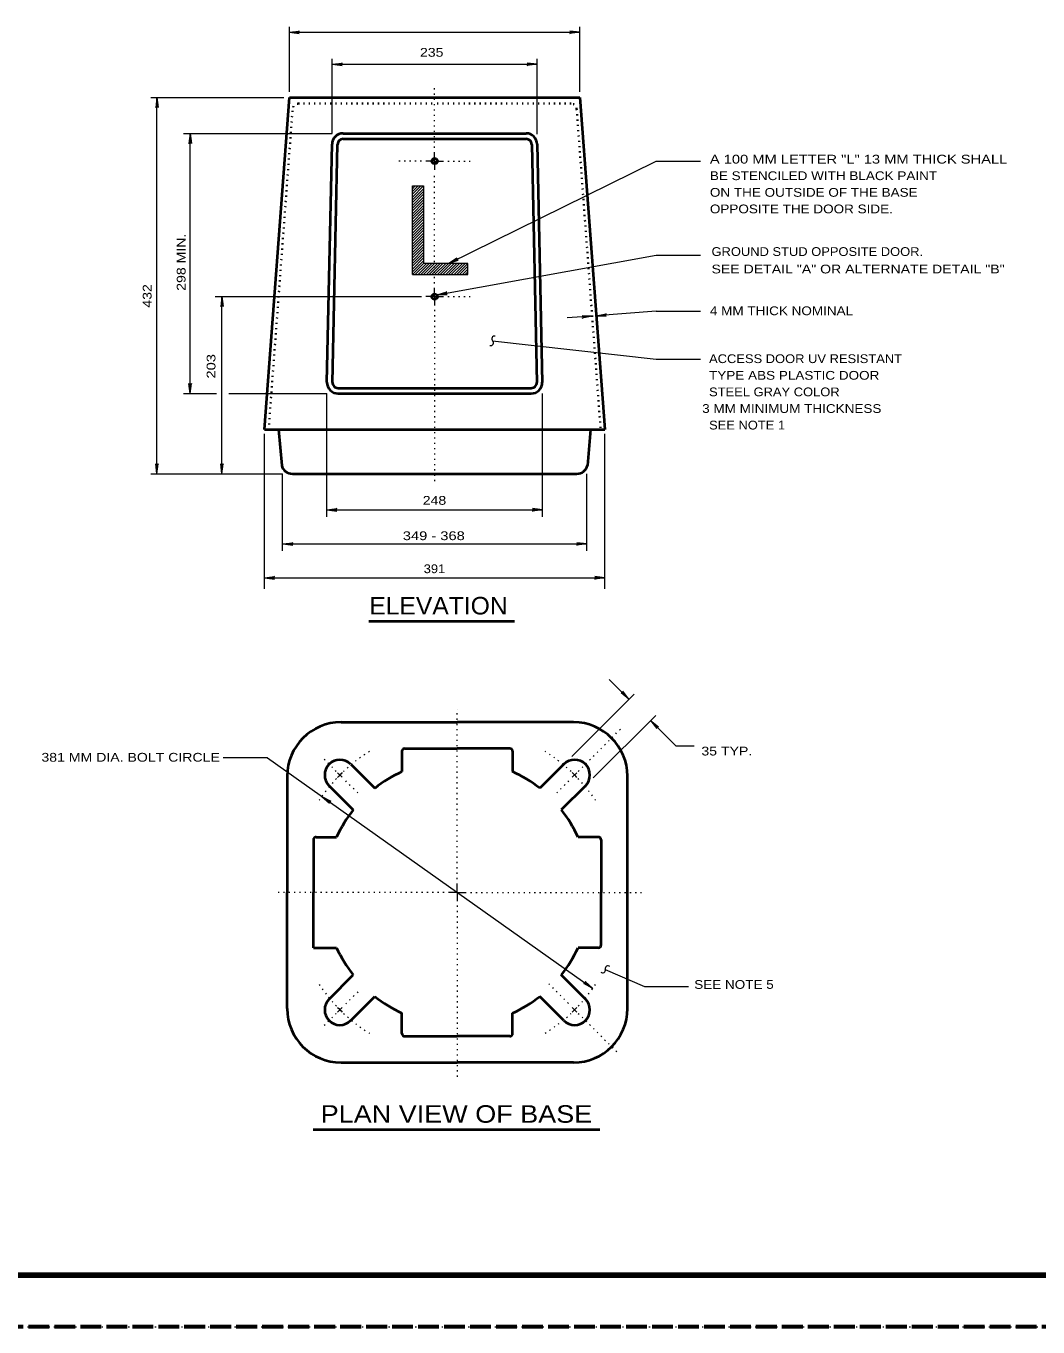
# Model space of a CAD drawing. Extents: x 312583 to 312854, y 144419 to 144597.
# Drawn here: x 312633.7 to 312721.4, y 144418.6 to 144531.2 of the extents above; entities that cross this region are included whole.
import ezdxf
from ezdxf.enums import TextEntityAlignment as Align

# ---------------------------------------------------------------- set-up
doc = ezdxf.new("R2010")
doc.units = 0
doc.header["$LTSCALE"] = 0.3
doc.linetypes.add('DOTTED', pattern=[1.5, 0.3, -1.2])
doc.linetypes.add('LONG_DASHED', pattern=[7.5, 6, -1.5])
for name, color, linetype, lineweight in [('1', 7, 'Continuous', 40), ('2', 7, 'Continuous', 13), ('62', 7, 'DOTTED', 13), ('63', 7, 'LONG_DASHED', 60)]:
    doc.layers.add(name, color=color, linetype=linetype, lineweight=lineweight)

msp = doc.modelspace()

# ---------------------------------------------------------------- linework, layer by layer
at = {"layer": '1', "linetype": 'DOTTED', "lineweight": 35}
for p in [(312657.3091, 144524.5084), (312680.9378, 144524.5084)]:
    msp.add_line(p, (312669.1235, 144524.5084), dxfattribs=at)
at = {"layer": '1'}
for p, q in [((312655.6148, 144496.295), (312655.8831, 144493.1824)), ((312682.6321, 144496.295), (312682.3638, 144493.1824)), ((312661.0266, 144470.9443), (312671.0853, 144470.9443)), ((312681.1516, 144470.9443), (312671.0853, 144470.9443)), ((312666.2936, 144468.4297), (312666.2936, 144466.6663)), ((312666.5313, 144468.675), (312671.0853, 144468.675)), ((312675.6393, 144468.675), (312671.0853, 144468.675)), ((312675.8769, 144468.4297), (312675.8769, 144466.6663)), ((312661.8546, 144467.3103), (312663.9399, 144465.225)), ((312680.3159, 144467.3103), (312678.2306, 144465.225)), ((312656.3499, 144466.2753), (312656.3499, 144456.2167)), ((312685.8206, 144456.2167), (312685.8206, 144466.2753)), ((312659.9916, 144465.4473), (312662.0769, 144463.362)), ((312682.1789, 144465.4473), (312680.0936, 144463.362)), ((312658.6269, 144460.763), (312658.6269, 144456.2167)), ((312658.8646, 144461.0083), (312660.6356, 144461.0083)), ((312683.3059, 144461.0083), (312681.5426, 144461.0083)), ((312683.5436, 144460.763), (312683.5436, 144456.2167)), ((312656.3499, 144446.1503), (312656.3499, 144456.2167)), ((312658.6269, 144451.425), (312658.6269, 144456.2167)), ((312683.5436, 144451.6627), (312683.5436, 144456.2167)), ((312685.8206, 144446.1503), (312685.8206, 144456.2167)), ((312658.6269, 144451.425), (312660.6356, 144451.425)), ((312683.3059, 144451.425), (312681.5426, 144451.425)), ((312659.9916, 144446.9783), (312662.0769, 144449.0713)), ((312682.1789, 144446.9783), (312680.0936, 144449.0637)), ((312661.8546, 144445.1153), (312663.9399, 144447.2007)), ((312680.3159, 144445.1153), (312678.2306, 144447.2007)), ((312666.2936, 144443.996), (312666.2936, 144445.7593)), ((312675.8769, 144443.996), (312675.8769, 144445.7593)), ((312666.5313, 144443.7583), (312671.0853, 144443.7583)), ((312675.6393, 144443.7583), (312671.0853, 144443.7583)), ((312661.0266, 144441.4813), (312671.0853, 144441.4813)), ((312681.1516, 144441.4813), (312671.0853, 144441.4813))]:
    msp.add_line(p, q, dxfattribs=at)
at = {"layer": '1', "linetype": 'DOTTED', "lineweight": 13}
for p, q in [((312681.5656, 144466.6893), (312685.3836, 144470.515)), ((312660.6049, 144466.6893), (312659.4933, 144467.8087)), ((312662.4756, 144464.8263), (312661.2336, 144466.0607)), ((312679.6949, 144464.8263), (312680.9369, 144466.0607)), ((312679.0049, 144448.297), (312680.9369, 144446.365)), ((312662.4756, 144447.5993), (312661.2336, 144446.365)), ((312660.6049, 144445.7363), (312659.4933, 144444.617)), ((312681.5656, 144445.7363), (312685.0003, 144442.3017))]:
    msp.add_line(p, q, dxfattribs=at)
at = {"layer": '1', "lineweight": 13}
for p, q in [((312661.1263, 144466.1757), (312660.7199, 144466.5743)), ((312681.0443, 144466.1757), (312681.4506, 144466.5743)), ((312661.1263, 144446.2577), (312660.7199, 144445.8513)), ((312681.0443, 144446.2577), (312681.4506, 144445.8513))]:
    msp.add_line(p, q, dxfattribs=at)
at = {"layer": '1', "lineweight": 158}
msp.add_line((312616.5, 144423.0846), (312849, 144423.0846), dxfattribs=at)
at = {"layer": '1'}
for centre in [(312669.1235, 144519.5308), (312669.1235, 144519.5308), (312669.1235, 144507.7912), (312669.1235, 144507.7912)]:
    msp.add_circle(centre, 0.2396, dxfattribs=at)
at = {"layer": '1', "linetype": 'DOTTED', "lineweight": 35}
for centre, start, end in [((312657.3071, 144524.0273), 90, 177.67414), ((312680.936, 144524.0273), 2.32586, 90)]:
    msp.add_arc(centre, 0.4792, start, end, dxfattribs=at)
at = {"layer": '1'}
for centre, radius, start, end in [((312656.812, 144493.4162), 0.9583, 194.04369, 270), ((312681.435, 144493.4162), 0.9583, 270, 345.95631), ((312661.0228, 144466.2753), 4.6719, 90, 180), ((312681.1478, 144466.2753), 4.6719, 0, 90), ((312666.5332, 144468.4316), 0.2396, 90, 180), ((312675.6373, 144468.4316), 0.2396, 0, 90), ((312660.9212, 144466.3769), 1.3177, 45, 225), ((312681.2493, 144466.3769), 1.3177, 315, 135), ((312671.0853, 144456.2128), 11.5, 114.62432, 128.42226), ((312671.0853, 144456.2128), 11.5, 51.58454, 65.37568), ((312671.0853, 144456.2128), 11.5, 141.59134, 155.37568), ((312671.0853, 144456.2128), 11.5, 24.62432, 38.41546), ((312658.8665, 144460.7649), 0.2396, 90, 180), ((312683.304, 144460.7649), 0.2396, 0, 90), ((312671.0853, 144456.2128), 11.5, 204.62432, 218.41546), ((312671.0853, 144456.2128), 11.5, 321.57774, 335.37568), ((312683.304, 144451.6608), 0.2396, 270, 0), ((312660.9212, 144446.0488), 1.3177, 135, 315), ((312671.0853, 144456.2128), 11.5, 231.58454, 245.37568), ((312671.0853, 144456.2128), 11.5, 294.62432, 308.40866), ((312681.2493, 144446.0488), 1.3177, 225, 45), ((312661.0228, 144446.1503), 4.6719, 180, 270), ((312681.1478, 144446.1503), 4.6719, 270, 0), ((312666.5332, 144443.9941), 0.2396, 180, 270), ((312675.6373, 144443.9941), 0.2396, 270, 0)]:
    msp.add_arc(centre, radius, start, end, dxfattribs=at)
at = {"layer": '1', "linetype": 'DOTTED', "lineweight": 13}
for start, end in [(121.96733, 133.24434), (46.75566, 58.03267), (136.75599, 146.30781), (33.69219, 43.24401), (213.69219, 223.24401), (316.75599, 326.30781), (226.75566, 238.03268), (301.96733, 313.24434)]:
    msp.add_arc((312671.0853, 144456.2128), 14.375, start, end, dxfattribs=at)
at = {"layer": '1', "lineweight": 13}
for start, end in [(133.83351, 136.1341), (43.8659, 46.16649), (223.8659, 226.16649), (313.83351, 316.1341)]:
    msp.add_arc((312671.0853, 144456.2128), 14.375, start, end, dxfattribs=at)
at = {"layer": '2'}
for p, q in [((312656.5425, 144525.5204), (312656.5425, 144531.163)), ((312681.7045, 144525.5204), (312681.7045, 144531.163)), ((312656.5195, 144530.6877), (312657.3858, 144530.795)), ((312656.5195, 144530.6877), (312681.7045, 144530.6877)), ((312656.5195, 144530.6877), (312657.3858, 144530.5804)), ((312657.3858, 144530.795), (312657.1098, 144530.6877)), ((312657.3858, 144530.5804), (312657.1098, 144530.6877)), ((312680.8381, 144530.795), (312681.1141, 144530.6877)), ((312681.7045, 144530.6877), (312680.8381, 144530.795)), ((312680.8381, 144530.5804), (312681.1141, 144530.6877)), ((312681.7045, 144530.6877), (312680.8381, 144530.5804)), ((312660.2608, 144521.9247), (312660.2608, 144528.3877)), ((312660.2608, 144527.9124), (312661.1271, 144528.0197)), ((312660.2608, 144527.9124), (312677.9938, 144527.9124)), ((312660.2608, 144527.9124), (312661.1271, 144527.805)), ((312661.1271, 144528.0197), (312660.8511, 144527.9124)), ((312661.1271, 144527.805), (312660.8511, 144527.9124)), ((312677.1275, 144528.0197), (312677.4035, 144527.9124)), ((312677.9938, 144527.9124), (312677.1275, 144528.0197)), ((312677.1275, 144527.805), (312677.4035, 144527.9124)), ((312677.9938, 144527.9124), (312677.1275, 144527.805)), ((312677.9938, 144521.8634), (312677.9938, 144528.3877)), ((312644.5595, 144525.045), (312656.0671, 144525.045)), ((312645.0808, 144525.045), (312644.9735, 144524.1787)), ((312644.9735, 144524.1787), (312645.0808, 144524.4547)), ((312645.0808, 144492.4617), (312645.0808, 144525.045)), ((312645.0808, 144525.045), (312645.1881, 144524.1787)), ((312645.1881, 144524.1787), (312645.0808, 144524.4547)), ((312647.3655, 144521.9247), (312660.2608, 144521.9247)), ((312647.9558, 144521.9247), (312647.8485, 144521.0584)), ((312647.8485, 144521.0584), (312647.9558, 144521.3344)), ((312647.9558, 144499.4077), (312647.9558, 144521.9247)), ((312647.9558, 144521.9247), (312648.0631, 144521.0584)), ((312648.0631, 144521.0584), (312647.9558, 144521.3344)), ((312669.1235, 144519.5327), (312669.1235, 144520.2994)), ((312669.1235, 144519.5327), (312669.1235, 144520.2994)), ((312669.1235, 144519.5327), (312668.3568, 144519.5327)), ((312669.1235, 144519.5327), (312669.8901, 144519.5327)), ((312669.1235, 144519.5327), (312669.1235, 144518.766)), ((312670.3271, 144510.67), (312688.3055, 144519.5174)), ((312688.3055, 144519.5174), (312692.1388, 144519.5174)), ((312667.2068, 144516.42), (312668.1651, 144517.3784)), ((312667.2068, 144516.6577), (312667.9275, 144517.3784)), ((312667.2068, 144516.8954), (312667.6898, 144517.3784)), ((312667.2068, 144517.133), (312667.4521, 144517.3784)), ((312667.2068, 144516.1747), (312668.1651, 144517.133)), ((312667.2068, 144515.937), (312668.1651, 144516.8954)), ((312667.2068, 144515.6994), (312668.1651, 144516.6577)), ((312667.2068, 144515.4617), (312668.1651, 144516.42)), ((312667.2068, 144515.2164), (312668.1651, 144516.1747)), ((312667.2068, 144514.9787), (312668.1651, 144515.937)), ((312667.2068, 144514.741), (312668.1651, 144515.6994)), ((312667.2068, 144514.5034), (312668.1651, 144515.4617)), ((312667.2068, 144514.258), (312668.1651, 144515.2164)), ((312667.2068, 144514.0204), (312668.1651, 144514.9787)), ((312667.2068, 144513.7827), (312668.1651, 144514.741)), ((312667.2068, 144513.545), (312668.1651, 144514.5034)), ((312667.2068, 144513.2997), (312668.1651, 144514.258)), ((312667.2068, 144513.062), (312668.1651, 144514.0204)), ((312667.2068, 144512.8244), (312668.1651, 144513.7827)), ((312667.2068, 144512.5867), (312668.1651, 144513.545)), ((312667.2068, 144512.3414), (312668.1651, 144513.2997)), ((312667.2068, 144512.1037), (312668.1651, 144513.062)), ((312667.2068, 144511.866), (312668.1651, 144512.8244)), ((312667.2068, 144511.6284), (312668.1651, 144512.5867)), ((312667.2068, 144511.383), (312668.1651, 144512.3414)), ((312667.2068, 144511.1454), (312668.1651, 144512.1037)), ((312667.2068, 144510.9077), (312668.1651, 144511.866)), ((312667.2068, 144510.67), (312668.1651, 144511.6284)), ((312667.2068, 144510.4247), (312668.1651, 144511.383)), ((312667.2068, 144510.187), (312668.1651, 144511.1454)), ((312667.2068, 144509.9494), (312668.1651, 144510.9077)), ((312669.3458, 144507.9407), (312688.3055, 144511.3754)), ((312670.3271, 144510.67), (312671.0555, 144511.1454)), ((312670.3271, 144510.67), (312671.1475, 144510.9537)), ((312671.0555, 144511.1454), (312670.8561, 144510.9307)), ((312671.1475, 144510.9537), (312670.8561, 144510.9307)), ((312688.3055, 144511.3754), (312692.1388, 144511.3754)), ((312667.2068, 144509.7117), (312668.1651, 144510.67)), ((312667.2068, 144509.7117), (312668.1651, 144510.67)), ((312667.2068, 144509.7117), (312668.1651, 144510.67)), ((312667.2068, 144509.7117), (312668.1651, 144510.67)), ((312667.2068, 144509.7117), (312668.1651, 144510.67)), ((312667.2068, 144509.7117), (312668.1651, 144510.67)), ((312667.2068, 144509.7117), (312668.1651, 144510.67)), ((312667.4521, 144509.7117), (312668.4105, 144510.67)), ((312667.6898, 144509.7117), (312668.6481, 144510.67)), ((312667.9275, 144509.7117), (312668.8858, 144510.67)), ((312668.1651, 144509.7117), (312669.1235, 144510.67)), ((312668.4105, 144509.7117), (312669.3688, 144510.67)), ((312668.6481, 144509.7117), (312669.6065, 144510.67)), ((312668.8858, 144509.7117), (312669.8441, 144510.67)), ((312669.1235, 144509.7117), (312670.0818, 144510.67)), ((312669.3688, 144509.7117), (312670.3271, 144510.67)), ((312669.6065, 144509.7117), (312670.5648, 144510.67)), ((312669.8441, 144509.7117), (312670.8025, 144510.67)), ((312670.0818, 144509.7117), (312671.0401, 144510.67)), ((312670.3271, 144509.7117), (312671.2855, 144510.67)), ((312670.5648, 144509.7117), (312671.5231, 144510.67)), ((312670.8025, 144509.7117), (312671.7608, 144510.67)), ((312671.0401, 144509.7117), (312671.9985, 144510.67)), ((312671.2855, 144509.7117), (312671.9985, 144510.4247)), ((312671.5231, 144509.7117), (312671.9985, 144510.187)), ((312671.7608, 144509.7117), (312671.9985, 144509.9494)), ((312669.1235, 144507.795), (312669.1235, 144508.5617)), ((312669.1235, 144507.795), (312669.1235, 144508.5617)), ((312650.1178, 144507.795), (312667.9735, 144507.795)), ((312650.7081, 144507.795), (312650.6008, 144506.9287)), ((312650.7081, 144492.4617), (312650.7081, 144507.795)), ((312650.7081, 144507.795), (312650.8155, 144506.9287)), ((312669.1235, 144507.795), (312668.3568, 144507.795)), ((312669.1235, 144507.795), (312669.1235, 144507.0284)), ((312669.1235, 144507.795), (312669.8901, 144507.795)), ((312669.3458, 144507.9407), (312670.1815, 144508.2014)), ((312669.3458, 144507.9407), (312670.2198, 144507.9944)), ((312670.1815, 144508.2014), (312669.9285, 144508.048)), ((312670.2198, 144507.9944), (312669.9285, 144508.048)), ((312650.6008, 144506.9287), (312650.7081, 144507.2047)), ((312650.8155, 144506.9287), (312650.7081, 144507.2047)), ((312688.3055, 144506.53), (312683.1228, 144506.139)), ((312683.1228, 144506.139), (312683.9738, 144506.3077)), ((312683.9738, 144506.3077), (312683.7055, 144506.1774)), ((312688.3055, 144506.53), (312692.1388, 144506.53)), ((312682.7625, 144506.1084), (312680.5851, 144505.9474)), ((312681.8885, 144506.1467), (312682.1721, 144506.0624)), ((312682.7625, 144506.1084), (312681.8885, 144506.1467)), ((312682.7625, 144506.1084), (312681.9038, 144505.9397)), ((312681.9038, 144505.9397), (312682.1721, 144506.0624)), ((312683.1228, 144506.139), (312683.9891, 144506.093)), ((312683.9891, 144506.093), (312683.7055, 144506.1774)), ((312647.8485, 144500.274), (312647.9558, 144499.998)), ((312647.9558, 144499.4077), (312647.8485, 144500.274)), ((312648.0631, 144500.274), (312647.9558, 144499.998)), ((312647.9558, 144499.4077), (312648.0631, 144500.274)), ((312647.3655, 144499.4077), (312650.2328, 144499.4077)), ((312651.2908, 144499.4077), (312659.7778, 144499.4077)), ((312659.7778, 144488.7204), (312659.7778, 144499.4077)), ((312678.4691, 144488.7204), (312678.4691, 144499.4077)), ((312654.3881, 144482.5027), (312654.3881, 144495.9194)), ((312683.8588, 144482.5027), (312683.8588, 144495.9194)), ((312644.9735, 144493.328), (312645.0808, 144493.052)), ((312645.0808, 144492.4617), (312644.9735, 144493.328)), ((312645.1881, 144493.328), (312645.0808, 144493.052)), ((312645.0808, 144492.4617), (312645.1881, 144493.328)), ((312650.6008, 144493.328), (312650.7081, 144493.052)), ((312650.7081, 144492.4617), (312650.6008, 144493.328)), ((312650.8155, 144493.328), (312650.7081, 144493.052)), ((312650.7081, 144492.4617), (312650.8155, 144493.328)), ((312644.5595, 144492.4617), (312655.9445, 144492.4617)), ((312655.9445, 144485.7917), (312655.9445, 144492.4617)), ((312682.3025, 144485.7917), (312682.3025, 144492.4617)), ((312659.7778, 144489.3337), (312660.6441, 144489.441)), ((312659.7778, 144489.3337), (312678.4691, 144489.3337)), ((312659.7778, 144489.3337), (312660.6441, 144489.2264)), ((312660.6441, 144489.441), (312660.3681, 144489.3337)), ((312660.6441, 144489.2264), (312660.3681, 144489.3337)), ((312677.6028, 144489.441), (312677.8788, 144489.3337)), ((312678.4691, 144489.3337), (312677.6028, 144489.441)), ((312677.6028, 144489.2264), (312677.8788, 144489.3337)), ((312678.4691, 144489.3337), (312677.6028, 144489.2264)), ((312655.9675, 144486.382), (312656.8338, 144486.4894)), ((312655.9675, 144486.382), (312682.3025, 144486.382)), ((312655.9675, 144486.382), (312656.8338, 144486.2747)), ((312656.8338, 144486.4894), (312656.5578, 144486.382)), ((312656.8338, 144486.2747), (312656.5578, 144486.382)), ((312681.4361, 144486.4894), (312681.7121, 144486.382)), ((312682.3025, 144486.382), (312681.4361, 144486.4894)), ((312681.4361, 144486.2747), (312681.7121, 144486.382)), ((312682.3025, 144486.382), (312681.4361, 144486.2747)), ((312654.3881, 144483.4534), (312655.2545, 144483.5607)), ((312654.3881, 144483.4534), (312683.8588, 144483.4534)), ((312654.3881, 144483.4534), (312655.2545, 144483.346)), ((312655.2545, 144483.5607), (312654.9785, 144483.4534)), ((312655.2545, 144483.346), (312654.9785, 144483.4534)), ((312682.9925, 144483.5607), (312683.2685, 144483.4534)), ((312683.8588, 144483.4534), (312682.9925, 144483.5607)), ((312682.9925, 144483.346), (312683.2685, 144483.4534)), ((312683.8588, 144483.4534), (312682.9925, 144483.346)), ((312685.9509, 144472.9453), (312684.2413, 144474.655)), ((312685.4143, 144473.6353), (312685.5369, 144473.3593)), ((312685.9509, 144472.9453), (312685.4143, 144473.6353)), ((312680.9906, 144467.985), (312686.3956, 144473.39)), ((312685.2609, 144473.482), (312685.5369, 144473.3593)), ((312685.9509, 144472.9453), (312685.2609, 144473.482)), ((312682.8613, 144466.122), (312688.2663, 144471.527)), ((312687.8139, 144471.0823), (312690.0066, 144468.8897)), ((312687.8139, 144471.0823), (312688.3506, 144470.3923)), ((312687.8139, 144471.0823), (312688.5039, 144470.5457)), ((312688.3506, 144470.3923), (312688.2356, 144470.6607)), ((312688.5039, 144470.5457), (312688.2356, 144470.6607)), ((312690.0066, 144468.8897), (312691.5859, 144468.8897)), ((312654.6556, 144467.87), (312650.8223, 144467.87)), ((312654.6556, 144467.87), (312682.8076, 144447.8983)), ((312659.3629, 144464.5273), (312660.0069, 144463.9447)), ((312659.3629, 144464.5273), (312660.1296, 144464.121)), ((312660.0069, 144463.9447), (312659.8459, 144464.19)), ((312660.1296, 144464.121), (312659.8459, 144464.19)), ((312671.0853, 144456.2167), (312671.0853, 144456.9833)), ((312671.0853, 144456.2167), (312670.3186, 144456.2167)), ((312671.0853, 144456.2167), (312671.8519, 144456.2167)), ((312671.0853, 144456.2167), (312671.0853, 144455.45)), ((312682.0409, 144448.3123), (312682.3323, 144448.2433)), ((312682.8076, 144447.8983), (312682.0409, 144448.3123)), ((312682.1636, 144448.4887), (312682.3323, 144448.2433)), ((312682.8076, 144447.8983), (312682.1636, 144448.4887))]:
    msp.add_line(p, q, dxfattribs=at)
at = {"layer": '2', "linetype": 'DOTTED'}
for p, q in [((312669.1235, 144520.6827), (312669.1235, 144525.988)), ((312667.9735, 144519.5327), (312665.7041, 144519.5327)), ((312670.2735, 144519.5327), (312672.2208, 144519.5327)), ((312669.1235, 144508.945), (312669.1235, 144518.467)), ((312670.2735, 144507.795), (312672.2208, 144507.795)), ((312669.1235, 144506.645), (312669.1235, 144491.534)), ((312671.0853, 144457.3667), (312671.0853, 144472.0867)), ((312669.9353, 144456.2167), (312655.2766, 144456.2167)), ((312672.2353, 144456.2167), (312687.0396, 144456.2167)), ((312671.0853, 144455.0667), (312671.0853, 144440.109))]:
    msp.add_line(p, q, dxfattribs=at)
at = {"layer": '2', "lineweight": 40}
for p, q in [((312654.3881, 144496.295), (312656.5425, 144525.045)), ((312656.5425, 144525.045), (312681.7045, 144525.045)), ((312681.7045, 144525.045), (312683.8588, 144496.295)), ((312659.8008, 144500.389), (312660.2378, 144520.9894)), ((312660.2761, 144500.3737), (312660.7208, 144520.9817)), ((312661.1961, 144521.9247), (312677.0508, 144521.9247)), ((312661.1961, 144521.4494), (312677.0508, 144521.4494)), ((312677.5261, 144520.9817), (312677.9708, 144500.3737)), ((312678.0091, 144520.9894), (312678.4461, 144500.366)), ((312660.7591, 144499.883), (312677.4878, 144499.883)), ((312660.7361, 144499.4077), (312677.4878, 144499.4077)), ((312654.3881, 144496.295), (312683.8588, 144496.295)), ((312656.8108, 144492.4617), (312681.4361, 144492.4617)), ((312663.4244, 144479.7044), (312676.0357, 144479.7044)), ((312658.6172, 144435.693), (312683.4194, 144435.693))]:
    msp.add_line(p, q, dxfattribs=at)
at = {"layer": '2', "linetype": 'DOTTED', "lineweight": 35}
for p, q in [((312654.7485, 144496.2644), (312656.8261, 144524.0484)), ((312681.4208, 144524.0484), (312683.4985, 144496.2644))]:
    msp.add_line(p, q, dxfattribs=at)
at = {"layer": '2'}
for points in [[(312667.2068, 144509.7117), (312667.2068, 144517.3784), (312668.1651, 144517.3784), (312668.1651, 144510.67)], [(312667.2068, 144509.7117), (312671.9985, 144509.7117), (312671.9985, 144510.67), (312668.1651, 144510.67)], [(312674.1451, 144503.9694), (312688.3055, 144502.3824), (312692.1388, 144502.3824)], [(312683.9039, 144449.5467), (312687.2849, 144448.0593), (312691.1183, 144448.0593)]]:
    msp.add_lwpolyline(points, dxfattribs=at)
at = {"layer": '2', "lineweight": 40}
for centre, radius, start, end in [((312661.1972, 144520.9683), 0.9583, 90, 178.76417), ((312661.1972, 144520.9683), 0.4792, 90, 178.76417), ((312677.0499, 144520.9683), 0.9583, 1.21751, 90), ((312677.0499, 144520.9683), 0.4792, 1.21751, 90), ((312660.7579, 144500.3641), 0.9583, 178.77642, 270), ((312660.7579, 144500.3641), 0.4792, 178.77642, 270), ((312677.488, 144500.3641), 0.9583, 270, 1.23789), ((312677.488, 144500.3641), 0.4792, 270, 1.23789)]:
    msp.add_arc(centre, radius, start, end, dxfattribs=at)
at = {"layer": '2'}
for centre, start, end in [((312673.9742, 144503.7988), 256.06269, 46.06269), ((312674.3065, 144504.1437), 76.06269, 226.06269), ((312683.6738, 144449.4804), 226.06269, 16.06269), ((312684.134, 144449.6129), 46.06269, 196.06269)]:
    msp.add_arc(centre, 0.2395, start, end, dxfattribs=at)
at = {"layer": '62'}
msp.add_lwpolyline([(312601.2, 144418.5846), (312853.5, 144418.5846), (312853.5, 144596.7846)], dxfattribs=at)
at = {"layer": '63'}
msp.add_line((312851.75, 144418.5846), (312583.526, 144418.5846), dxfattribs=at)

# ---------------------------------------------------------------- texts
at = {"layer": '2'}
for s, width, p in [('235 ', 1.2, (312667.8535, 144528.5678)), ('A 100 MM LETTER "L" 13 MM THICK SHALL', 1.25, (312692.957, 144519.3187)), ('BE STENCILED WITH BLACK PAINT', 1.15, (312692.957, 144517.885)), ('ON THE OUTSIDE OF THE BASE', 1.15, (312692.957, 144516.4437)), ('OPPOSITE THE DOOR SIDE.', 1.15, (312692.957, 144515.01)), ('GROUND STUD OPPOSITE DOOR.', 1.1, (312693.0971, 144511.317)), ('SEE DETAIL "A" OR ALTERNATE DETAIL "B"', 1.2, (312693.0971, 144509.8055)), ('4 MM THICK NOMINAL', 1.15, (312692.957, 144506.191)), ('ACCESS DOOR UV RESISTANT', 1.1, (312692.8869, 144502.0434)), ('TYPE ABS PLASTIC DOOR', 1.15, (312692.8869, 144500.602)), ('STEEL GRAY COLOR', 1.1, (312692.8869, 144499.1684)), (' 3 MM MINIMUM THICKNESS', 1.15, (312691.9669, 144497.727)), ('SEE NOTE 1', 1.1, (312692.8869, 144496.2934)), ('248 ', 1.2, (312668.0924, 144489.7748)), ('349 - 368 ', 1.25, (312666.3674, 144486.7134)), ('391  ', 1.1, (312668.1773, 144483.855)), ('381 MM DIA. BOLT CIRCLE', 1.2, (312635.0739, 144467.5309)), ('35 TYP.', 1.2, (312692.2223, 144468.0683)), ('SEE NOTE 5', 1.15, (312691.6013, 144447.8606))]:
    msp.add_text(s, height=0.76, dxfattribs=dict(at, width=width)).set_placement(p)
for s, width, p in [('298 MIN.', 1.2, (312647.5552, 144508.3017)), ('432 ', 1.2, (312644.6101, 144506.8425)), ('203 ', 1.25, (312650.1433, 144500.7041))]:
    msp.add_text(s, height=0.76, rotation=90, dxfattribs=dict(at, width=width)).set_placement(p)
for s, width, p in [('ELEVATION', 1.05, (312669.4555, 144480.2778)), ('PLAN VIEW OF BASE', 1.15, (312671.0139, 144436.2664))]:
    msp.add_text(s, height=1.52, dxfattribs=dict(at, width=width)).set_placement(p, align=Align.CENTER)

doc.saveas('drawing.dxf')
